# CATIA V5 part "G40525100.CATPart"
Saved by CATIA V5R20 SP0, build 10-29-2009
Part number: G40525100
Revision: 9
Definition: design
Nomenclature: G40525100
Source: made
Description: NOT SPECIFIED
Bounding box of the stored display mesh (mm): x -50 to 50, y -12.5 to 12.5, z -25 to 0
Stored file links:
  C:\Users\Raffaele\Desktop\3D X SITO CF\BOLEX\29-GUIDE STRIP REF 405\G40525100.CATPart
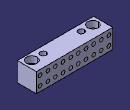
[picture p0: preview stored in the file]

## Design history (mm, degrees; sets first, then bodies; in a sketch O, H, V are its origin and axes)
Body1 "MANIFOLD_SOLID_BREP #3622" (main body)
  Solid1: solid without history
Body2 "MANIFOLD_SOLID_BREP #3760"
  Solid2: solid without history
Body3 "MANIFOLD_SOLID_BREP #3872"
  Solid3: solid without history
Body4 "MANIFOLD_SOLID_BREP #3984"
  Solid4: solid without history
Body5 "MANIFOLD_SOLID_BREP #4096"
  Solid5: solid without history
Body6 "MANIFOLD_SOLID_BREP #4208"
  Solid6: solid without history
Body7 "MANIFOLD_SOLID_BREP #4320"
  Solid7: solid without history
Body8 "MANIFOLD_SOLID_BREP #4432"
  Solid8: solid without history
Body9 "MANIFOLD_SOLID_BREP #4544"
  Solid9: solid without history
Body10 "MANIFOLD_SOLID_BREP #4656"
  Solid10: solid without history
Body11 "MANIFOLD_SOLID_BREP #4768"
  Solid11: solid without history
Body12 "MANIFOLD_SOLID_BREP #4880"
  Solid12: solid without history
Body13 "MANIFOLD_SOLID_BREP #4992"
  Solid13: solid without history
Body14 "MANIFOLD_SOLID_BREP #5104"
  Solid14: solid without history
Body15 "MANIFOLD_SOLID_BREP #5216"
  Solid15: solid without history
Body16 "MANIFOLD_SOLID_BREP #5328"
  Solid16: solid without history
Body17 "MANIFOLD_SOLID_BREP #5440"
  Solid17: solid without history
Body18 "MANIFOLD_SOLID_BREP #5552"
  Solid18: solid without history
Body19 "MANIFOLD_SOLID_BREP #5664"
  Solid19: solid without history
Body20 "MANIFOLD_SOLID_BREP #5776"
  Solid20: solid without history
Body21 "MANIFOLD_SOLID_BREP #5914"
  Solid21: solid without history
Body22 "MANIFOLD_SOLID_BREP #6052"
  Solid22: solid without history
Body23 "MANIFOLD_SOLID_BREP #6190"
  Solid23: solid without history
Body24 "MANIFOLD_SOLID_BREP #6328"
  Solid24: solid without history
Body25 "MANIFOLD_SOLID_BREP #6466"
  Solid25: solid without history
Body26 "MANIFOLD_SOLID_BREP #6604"
  Solid26: solid without history
Body27 "MANIFOLD_SOLID_BREP #6742"
  Solid27: solid without history
Body28 "MANIFOLD_SOLID_BREP #6880"
  Solid28: solid without history
Body29 "MANIFOLD_SOLID_BREP #6992"
  Solid29: solid without history
Body30 "MANIFOLD_SOLID_BREP #7104"
  Solid30: solid without history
